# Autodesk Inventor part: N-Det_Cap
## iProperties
Shininess: 64.0
Length Units: 11272
Angle Units: 11279
Time Units: 11290
Mass Units: 11286
Length Display Precision: 3
Angle Display Precision: 2
Compacted: True
Part Number: N-Det_Cap
Document SubType Name: Modeling
Created: 2005-05
Designer: John Blackburn
Material: Aluminum-6061
Manufacturer: Standard
Standards Organization: Custom
Density: 0.0
Volumn: 0.0
Area: 0.0
PropertySet Name: Model Information
Control State: 0
Master: False
Checked Out: False
Author: John Blackburn
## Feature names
1. Extrusion1
2. Hole1
